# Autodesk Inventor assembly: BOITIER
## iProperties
Created: 2011-01
Part Number: BOITIER
Document SubType Name: Assembly
Designer: eric
Mass: 1354.24 g
Surface Area: 8423.69 cm^2
Volume: 1354.24 cm^3
Density: 1 g/cm^3
Norme de conversion: IGES 5.3
Nom du fichier: No Iges File Name specified
Préprocesseur: Autodesk Inventor 2011
Postprocesseur: Build: 342, Release: 2008 SP3 - Date: Tue 05/27/2008
Unités envoyées: MM
Incertitude: 0.01
Author: eric
